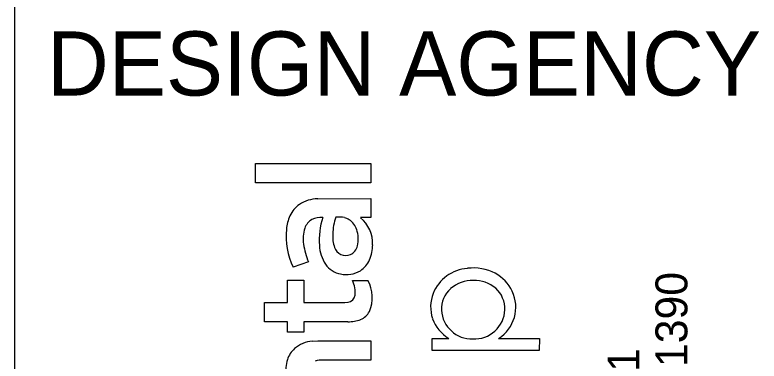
# Model space of a CAD drawing. Extents: x 0 to 34, y 0 to 22.
# Drawn here: x 32 to 33.162, y 3.936 to 4.476 of the extents above; entities that cross this region are included whole.
import ezdxf

# ---------------------------------------------------------------- set-up
doc = ezdxf.new("R2010")
doc.units = 0
doc.layers.add('SH_Border', color=7, linetype='Continuous')
doc.layers.add('SH_Data', color=7, linetype='Continuous')

msp = doc.modelspace()

# ---------------------------------------------------------------- linework, layer by layer
at = {"layer": 'SH_Border'}
msp.add_line((32, 0.5), (32, 21.5), dxfattribs=at)
at = {"layer": 'SH_Data'}
for p, q in [((32.3756, 4.2141), (32.3756, 4.244)), ((32.3756, 4.244), (32.5557, 4.244)), ((32.5557, 4.244), (32.5557, 4.2141)), ((32.5557, 4.2141), (32.3756, 4.2141)), ((32.4727, 4.189), (32.5555, 4.1892)), ((32.5555, 4.1892), (32.5557, 4.1596)), ((32.5557, 4.1596), (32.5397, 4.1596)), ((32.4582, 4.0904), (32.4343, 4.0823)), ((32.4254, 4.027), (32.4255, 4.0621)), ((32.4255, 4.0621), (32.4511, 4.0621)), ((32.4511, 4.0621), (32.4512, 4.027)), ((32.527, 4.0616), (32.5511, 4.0616)), ((32.3896, 3.9972), (32.3896, 4.027)), ((32.3896, 4.027), (32.4254, 4.027)), ((32.4512, 4.027), (32.515, 4.027)), ((32.515, 4.027), (32.52, 4.0275)), ((32.4254, 3.9972), (32.3896, 3.9972)), ((32.4254, 3.9807), (32.4254, 3.9972)), ((32.5197, 3.9972), (32.4511, 3.9972)), ((32.4511, 3.9972), (32.4511, 3.9807)), ((32.4511, 3.9807), (32.4254, 3.9807)), ((32.4644, 3.9669), (32.4729, 3.9673)), ((32.4729, 3.9673), (32.5557, 3.9673)), ((32.5557, 3.9673), (32.5557, 3.9375)), ((32.6515, 3.9521), (32.6515, 3.9711)), ((32.6515, 3.9711), (32.6771, 3.9711)), ((32.7549, 3.9713), (32.8186, 3.9711)), ((32.8186, 3.9711), (32.8184, 3.9521)), ((32.8184, 3.9521), (32.6515, 3.9521)), ((32.5557, 3.9375), (32.4814, 3.9375))]:
    msp.add_line(p, q, dxfattribs=at)
msp.add_lwpolyline([(32.3756, 4.2141), (32.3756, 4.244), (32.5557, 4.244), (32.5557, 4.2141)], close=True, dxfattribs=at)
for points in [[(32.4727, 4.189), (32.5555, 4.1892), (32.5557, 4.1596)], [(32.5557, 4.1596), (32.5397, 4.1596)], [(32.4582, 4.0904), (32.4343, 4.0823)], [(32.5197, 3.9972), (32.4511, 3.9972), (32.4511, 3.9807), (32.4254, 3.9807), (32.4254, 3.9972), (32.3896, 3.9972), (32.3896, 4.027), (32.4254, 4.027), (32.4255, 4.0621), (32.4511, 4.0621), (32.4512, 4.027), (32.515, 4.027), (32.52, 4.0275)], [(32.527, 4.0616), (32.5511, 4.0616)], [(32.4644, 3.9669), (32.4729, 3.9673), (32.5557, 3.9673), (32.5557, 3.9375), (32.4814, 3.9375)], [(32.7549, 3.9713), (32.8186, 3.9711), (32.8184, 3.9521), (32.6515, 3.9521)], [(32.6515, 3.9521), (32.6515, 3.9711), (32.6771, 3.9711)]]:
    msp.add_lwpolyline(points, dxfattribs=at)
for centre, radius, start, end in [((32.4745, 4.1326), 0.0565, 91.8942, 122.6317), ((32.4745, 4.1326), 0.0565, 91.8942, 122.6317), ((32.4685, 4.1447), 0.043, 124.537, 155.6594), ((32.4685, 4.1447), 0.043, 124.537, 155.6594), ((32.4882, 4.1361), 0.0646, 155.9764, 175.3149), ((32.4882, 4.1361), 0.0646, 155.9764, 175.3149), ((32.4779, 4.1278), 0.0321, 85.3802, 116.6222), ((32.4779, 4.1278), 0.0321, 85.3802, 116.6222), ((32.5879, 4.1251), 0.1129, 162.0821, 184.5285), ((32.5879, 4.1251), 0.1129, 162.0821, 184.5285), ((32.5801, 4.1313), 0.0841, 159.8366, 178.0362), ((32.5801, 4.1313), 0.0841, 159.8366, 178.0362), ((32.5051, 4.1074), 0.053, 79.6696, 94.2322), ((32.5051, 4.1074), 0.053, 79.6696, 94.2322), ((32.5089, 4.1364), 0.0238, 56.8913, 76.2149), ((32.5089, 4.1364), 0.0238, 56.8913, 76.2149), ((32.5055, 4.1191), 0.0529, 358.0746, 49.762), ((32.5055, 4.1191), 0.0529, 358.0746, 49.762), ((32.4753, 4.1356), 0.024, 119.4252, 161.6629), ((32.4753, 4.1356), 0.024, 119.4252, 161.6629), ((32.5052, 4.1318), 0.0297, 17.5984, 55.7282), ((32.5052, 4.1318), 0.0297, 17.5984, 55.7282), ((32.5364, 4.1308), 0.113, 174.6101, 205.3899), ((32.5364, 4.1308), 0.113, 174.6101, 205.3899), ((32.5076, 4.1265), 0.0576, 163.1369, 188.1675), ((32.5076, 4.1265), 0.0576, 163.1369, 188.1675), ((32.4916, 4.1264), 0.0443, 345.9408, 18.9919), ((32.4916, 4.1264), 0.0443, 345.9408, 18.9919), ((32.5466, 4.1303), 0.0506, 175.5903, 199.8857), ((32.5466, 4.1303), 0.0506, 175.5903, 199.8857), ((32.5473, 4.1297), 0.0973, 186.7598, 203.7981), ((32.5473, 4.1297), 0.0973, 186.7598, 203.7981), ((32.5328, 4.1187), 0.0575, 182.5676, 213.7144), ((32.5328, 4.1187), 0.0575, 182.5676, 213.7144), ((32.5164, 4.1189), 0.0184, 198.2844, 293.3081), ((32.5164, 4.1189), 0.0184, 198.2844, 293.3081), ((32.5152, 4.1199), 0.0199, 295.2883, 347.4639), ((32.5152, 4.1199), 0.0199, 295.2883, 347.4639), ((32.5019, 4.1168), 0.0566, 336.016, 0.5951), ((32.5019, 4.1168), 0.0566, 336.016, 0.5951), ((32.5175, 4.1097), 0.0394, 303.4436, 336.18), ((32.5175, 4.1097), 0.0394, 303.4436, 336.18), ((32.5149, 4.1078), 0.0366, 215.0668, 259.8133), ((32.5149, 4.1078), 0.0366, 215.0668, 259.8133), ((32.7108, 4.0182), 0.0624, 93.9866, 158.3119), ((32.7108, 4.0182), 0.0624, 93.9866, 158.3119), ((32.7156, 4.0065), 0.0746, 62.6889, 97.0135), ((32.7156, 4.0065), 0.0746, 62.6889, 97.0135), ((32.5175, 4.1131), 0.0423, 257.5256, 300.882), ((32.5175, 4.1131), 0.0423, 257.5256, 300.882), ((32.7212, 4.0191), 0.0608, 25.0657, 61.9602), ((32.7212, 4.0191), 0.0608, 25.0657, 61.9602), ((32.4863, 4.042), 0.0452, 10.1545, 25.723), ((32.4863, 4.042), 0.0452, 10.1545, 25.723), ((32.503, 4.0351), 0.0549, 336.589, 28.8991), ((32.503, 4.0351), 0.0549, 336.589, 28.8991), ((32.7138, 4.0102), 0.0513, 87.8965, 131.1812), ((32.7138, 4.0102), 0.0513, 87.8965, 131.1812), ((32.7175, 4.0102), 0.0513, 49.9089, 92.0363), ((32.7175, 4.0102), 0.0513, 49.9089, 92.0363), ((32.4957, 4.0436), 0.0356, 351.914, 10.2059), ((32.4957, 4.0436), 0.0356, 351.914, 10.2059), ((32.7092, 4.0167), 0.0434, 132.3289, 182.0949), ((32.7092, 4.0167), 0.0434, 132.3289, 182.0949), ((32.7215, 4.0173), 0.0433, 358.0487, 47.9447), ((32.7215, 4.0173), 0.0433, 358.0487, 47.9447), ((32.7245, 4.02), 0.0574, 301.9776, 25.6418), ((32.7245, 4.02), 0.0574, 301.9776, 25.6418), ((32.5184, 4.04), 0.0126, 277.6142, 353.7918), ((32.5184, 4.04), 0.0126, 277.6142, 353.7918), ((32.707, 4.0202), 0.0581, 158.656, 198.171), ((32.707, 4.0202), 0.0581, 158.656, 198.171), ((32.5291, 4.0261), 0.0275, 292.6889, 332.0598), ((32.5291, 4.0261), 0.0275, 292.6889, 332.0598), ((32.7135, 4.0181), 0.0478, 183.5974, 271.7045), ((32.7135, 4.0181), 0.0478, 183.5974, 271.7045), ((32.7172, 4.018), 0.0477, 267.3149, 357.4019), ((32.7172, 4.018), 0.0477, 267.3149, 357.4019), ((32.5209, 4.0486), 0.0514, 268.6727, 291.5235), ((32.5209, 4.0486), 0.0514, 268.6727, 291.5235), ((32.7103, 4.0243), 0.0627, 200.8399, 238.0162), ((32.7103, 4.0243), 0.0627, 200.8399, 238.0162), ((32.4687, 3.9172), 0.0499, 94.9706, 130.2248), ((32.4687, 3.9172), 0.0499, 94.9706, 130.2248), ((32.4635, 3.9255), 0.0402, 132.2238, 161.6823), ((32.4635, 3.9255), 0.0402, 132.2238, 161.6823), ((32.4787, 3.9211), 0.056, 162.274, 187.7917), ((32.4787, 3.9211), 0.056, 162.274, 187.7917), ((32.4811, 3.8915), 0.046, 89.6051, 105.3303), ((32.4811, 3.8915), 0.046, 89.6051, 105.3303)]:
    msp.add_arc(centre, radius, start, end, dxfattribs=at)

# ---------------------------------------------------------------- texts
msp.add_text('DESIGN AGENCY', height=0.1, dxfattribs=at).set_placement((32.05, 4.35))
for s, p in [('800.835.1390', (33.0497, 3.6671)), ('450 GRANT ST., AKRON, OH  44311', (32.9749, 2.8374))]:
    msp.add_text(s, height=0.049846, rotation=90, dxfattribs=at).set_placement(p)

doc.saveas('drawing.dxf')
